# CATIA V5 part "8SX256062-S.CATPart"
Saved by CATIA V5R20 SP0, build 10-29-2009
Part number: 8SX256062-S
Revision: ANY
Definition: UNKNOWN
Nomenclature: 8SX256062-S
Source: Unknown
Bounding box of the stored display mesh (mm): x -5 to 5, y 11.558 to 21.5, z 0 to 12
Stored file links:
  C:\Users\Utente\Desktop\IO LAVORO\3D X SITO CF\CUMSA\3D files SX.256062\SX 256062\8SX256062-S.CATPart
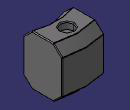
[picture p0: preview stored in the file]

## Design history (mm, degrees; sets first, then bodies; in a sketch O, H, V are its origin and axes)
Body1 "Redondeo1" (main body)
  Solid1: solid without history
